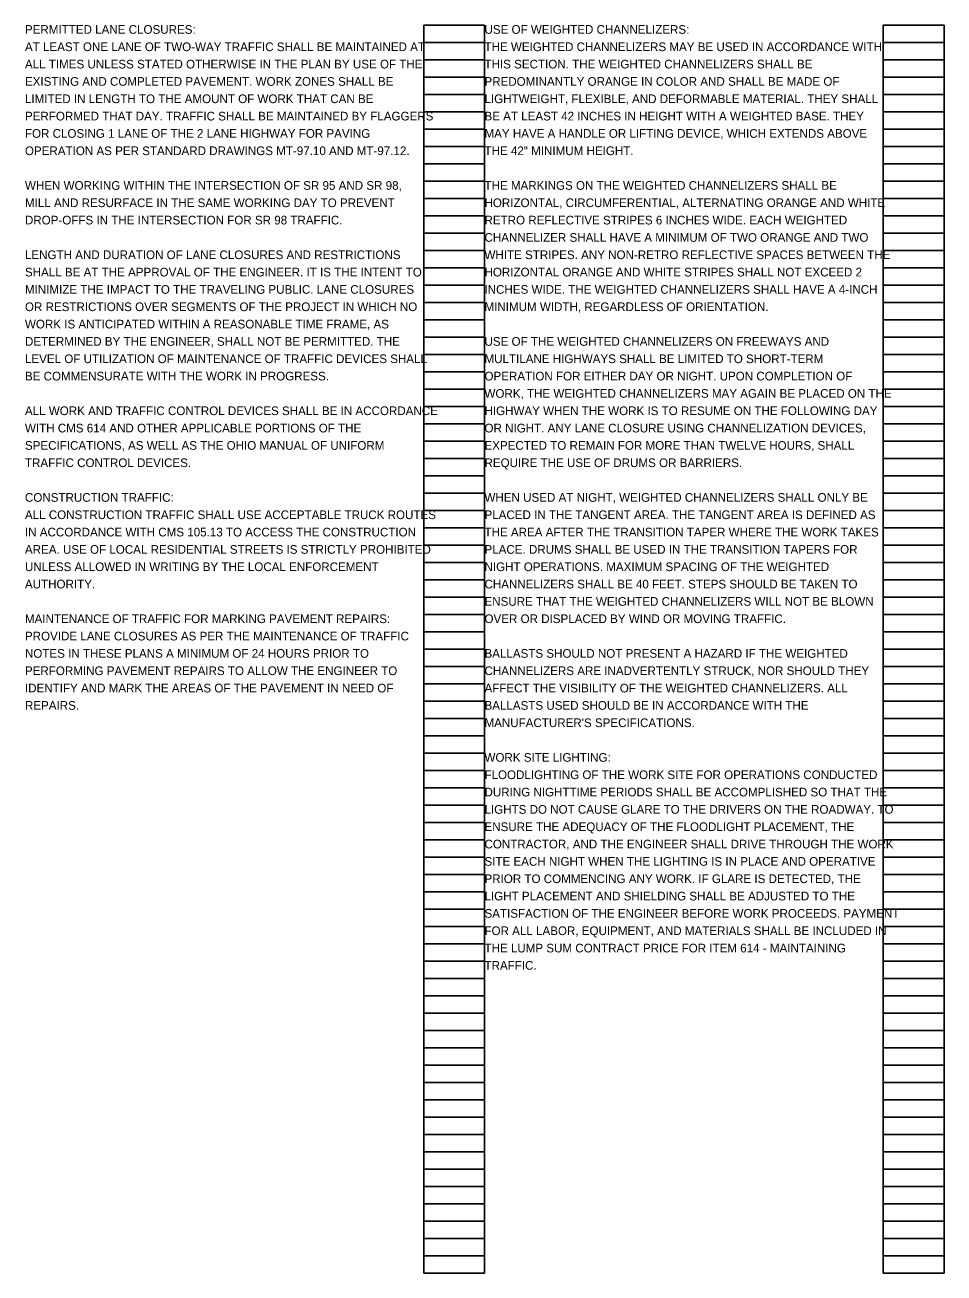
# Model space of a CAD drawing. Extents: x -23 to 32, y -58.1 to 21.1.
# Drawn here: x 2.4 to 17.24, y -28.09 to -7.93 of the extents above; entities that cross this region are included whole.
import ezdxf

# ---------------------------------------------------------------- set-up
doc = ezdxf.new("R2010")
doc.units = 0
doc.layers.add('SH_Data', color=7, linetype='Continuous')
doc.layers.add('SH_Text', color=7, linetype='Continuous')

msp = doc.modelspace()

# ---------------------------------------------------------------- linework, layer by layer
at = {"layer": 'SH_Data'}
for p, q in [((8.84, -28.093), (8.84, -7.933)), ((8.84, -7.933), (9.82, -7.933)), ((9.82, -28.093), (9.82, -7.933)), ((16.26, -28.093), (16.26, -7.933)), ((16.26, -7.933), (17.24, -7.933)), ((17.24, -28.093), (17.24, -7.933)), ((8.84, -8.213), (9.82, -8.213)), ((16.26, -8.213), (17.24, -8.213)), ((8.84, -8.493), (9.82, -8.493)), ((16.26, -8.493), (17.24, -8.493)), ((8.84, -8.773), (9.82, -8.773)), ((16.26, -8.773), (17.24, -8.773)), ((8.84, -9.053), (9.82, -9.053)), ((16.26, -9.053), (17.24, -9.053)), ((8.84, -9.333), (9.82, -9.333)), ((16.26, -9.333), (17.24, -9.333)), ((8.84, -9.613), (9.82, -9.613)), ((16.26, -9.613), (17.24, -9.613)), ((8.84, -9.893), (9.82, -9.893)), ((16.26, -9.893), (17.24, -9.893)), ((8.84, -10.173), (9.82, -10.173)), ((16.26, -10.173), (17.24, -10.173)), ((8.84, -10.453), (9.82, -10.453)), ((16.26, -10.453), (17.24, -10.453)), ((8.84, -10.733), (9.82, -10.733)), ((16.26, -10.733), (17.24, -10.733)), ((8.84, -11.013), (9.82, -11.013)), ((16.26, -11.013), (17.24, -11.013)), ((8.84, -11.293), (9.82, -11.293)), ((16.26, -11.293), (17.24, -11.293)), ((8.84, -11.573), (9.82, -11.573)), ((16.26, -11.573), (17.24, -11.573)), ((8.84, -11.853), (9.82, -11.853)), ((16.26, -11.853), (17.24, -11.853)), ((8.84, -12.133), (9.82, -12.133)), ((16.26, -12.133), (17.24, -12.133)), ((8.84, -12.413), (9.82, -12.413)), ((16.26, -12.413), (17.24, -12.413)), ((8.84, -12.693), (9.82, -12.693)), ((16.26, -12.693), (17.24, -12.693)), ((8.84, -12.973), (9.82, -12.973)), ((16.26, -12.973), (17.24, -12.973)), ((8.84, -13.253), (9.82, -13.253)), ((16.26, -13.253), (17.24, -13.253)), ((8.84, -13.533), (9.82, -13.533)), ((16.26, -13.533), (17.24, -13.533)), ((8.84, -13.813), (9.82, -13.813)), ((16.26, -13.813), (17.24, -13.813)), ((8.84, -14.093), (9.82, -14.093)), ((16.26, -14.093), (17.24, -14.093)), ((8.84, -14.373), (9.82, -14.373)), ((16.26, -14.373), (17.24, -14.373)), ((8.84, -14.653), (9.82, -14.653)), ((16.26, -14.653), (17.24, -14.653)), ((8.84, -14.933), (9.82, -14.933)), ((16.26, -14.933), (17.24, -14.933)), ((8.84, -15.213), (9.82, -15.213)), ((16.26, -15.213), (17.24, -15.213)), ((8.84, -15.493), (9.82, -15.493)), ((16.26, -15.493), (17.24, -15.493)), ((8.84, -15.773), (9.82, -15.773)), ((16.26, -15.773), (17.24, -15.773)), ((8.84, -16.053), (9.82, -16.053)), ((16.26, -16.053), (17.24, -16.053)), ((8.84, -16.333), (9.82, -16.333)), ((16.26, -16.333), (17.24, -16.333)), ((8.84, -16.613), (9.82, -16.613)), ((16.26, -16.613), (17.24, -16.613)), ((8.84, -16.893), (9.82, -16.893)), ((16.26, -16.893), (17.24, -16.893)), ((8.84, -17.173), (9.82, -17.173)), ((16.26, -17.173), (17.24, -17.173)), ((8.84, -17.453), (9.82, -17.453)), ((16.26, -17.453), (17.24, -17.453)), ((8.84, -17.733), (9.82, -17.733)), ((16.26, -17.733), (17.24, -17.733)), ((8.84, -18.013), (9.82, -18.013)), ((16.26, -18.013), (17.24, -18.013)), ((8.84, -18.293), (9.82, -18.293)), ((16.26, -18.293), (17.24, -18.293)), ((8.84, -18.573), (9.82, -18.573)), ((16.26, -18.573), (17.24, -18.573)), ((8.84, -18.853), (9.82, -18.853)), ((16.26, -18.853), (17.24, -18.853)), ((8.84, -19.133), (9.82, -19.133)), ((16.26, -19.133), (17.24, -19.133)), ((8.84, -19.413), (9.82, -19.413)), ((16.26, -19.413), (17.24, -19.413)), ((8.84, -19.693), (9.82, -19.693)), ((16.26, -19.693), (17.24, -19.693)), ((8.84, -19.973), (9.82, -19.973)), ((16.26, -19.973), (17.24, -19.973)), ((8.84, -20.253), (9.82, -20.253)), ((16.26, -20.253), (17.24, -20.253)), ((8.84, -20.533), (9.82, -20.533)), ((16.26, -20.533), (17.24, -20.533)), ((8.84, -20.813), (9.82, -20.813)), ((16.26, -20.813), (17.24, -20.813)), ((8.84, -21.093), (9.82, -21.093)), ((16.26, -21.093), (17.24, -21.093)), ((8.84, -21.373), (9.82, -21.373)), ((16.26, -21.373), (17.24, -21.373)), ((8.84, -21.653), (9.82, -21.653)), ((16.26, -21.653), (17.24, -21.653)), ((8.84, -21.933), (9.82, -21.933)), ((16.26, -21.933), (17.24, -21.933)), ((8.84, -22.213), (9.82, -22.213)), ((16.26, -22.213), (17.24, -22.213)), ((8.84, -22.493), (9.82, -22.493)), ((16.26, -22.493), (17.24, -22.493)), ((8.84, -22.773), (9.82, -22.773)), ((16.26, -22.773), (17.24, -22.773)), ((8.84, -23.053), (9.82, -23.053)), ((16.26, -23.053), (17.24, -23.053)), ((8.84, -23.333), (9.82, -23.333)), ((16.26, -23.333), (17.24, -23.333)), ((8.84, -23.613), (9.82, -23.613)), ((16.26, -23.613), (17.24, -23.613)), ((8.84, -23.893), (9.82, -23.893)), ((16.26, -23.893), (17.24, -23.893)), ((8.84, -24.173), (9.82, -24.173)), ((16.26, -24.173), (17.24, -24.173)), ((8.84, -24.453), (9.82, -24.453)), ((16.26, -24.453), (17.24, -24.453)), ((8.84, -24.733), (9.82, -24.733)), ((16.26, -24.733), (17.24, -24.733)), ((8.84, -25.013), (9.82, -25.013)), ((16.26, -25.013), (17.24, -25.013)), ((8.84, -25.293), (9.82, -25.293)), ((16.26, -25.293), (17.24, -25.293)), ((8.84, -25.573), (9.82, -25.573)), ((16.26, -25.573), (17.24, -25.573)), ((8.84, -25.853), (9.82, -25.853)), ((16.26, -25.853), (17.24, -25.853)), ((8.84, -26.133), (9.82, -26.133)), ((16.26, -26.133), (17.24, -26.133)), ((8.84, -26.413), (9.82, -26.413)), ((16.26, -26.413), (17.24, -26.413)), ((8.84, -26.693), (9.82, -26.693)), ((16.26, -26.693), (17.24, -26.693)), ((8.84, -26.973), (9.82, -26.973)), ((16.26, -26.973), (17.24, -26.973)), ((8.84, -27.253), (9.82, -27.253)), ((16.26, -27.253), (17.24, -27.253)), ((8.84, -27.533), (9.82, -27.533)), ((16.26, -27.533), (17.24, -27.533)), ((8.84, -27.813), (9.82, -27.813)), ((16.26, -27.813), (17.24, -27.813)), ((8.84, -28.093), (9.82, -28.093)), ((16.26, -28.093), (17.24, -28.093))]:
    msp.add_line(p, q, dxfattribs=at)

# ---------------------------------------------------------------- texts
at = {"layer": 'SH_Text'}
for s, p in [('PERMITTED LANE CLOSURES:', (2.4, -8.073)), ('USE OF WEIGHTED CHANNELIZERS:', (9.82, -8.073)), ('AT LEAST ONE LANE OF TWO-WAY TRAFFIC SHALL BE MAINTAINED AT ', (2.4, -8.353)), ('THE WEIGHTED CHANNELIZERS MAY BE USED IN ACCORDANCE WITH ', (9.82, -8.353)), ('ALL TIMES UNLESS STATED OTHERWISE IN THE PLAN BY USE OF THE ', (2.4, -8.633)), ('THIS SECTION. THE WEIGHTED CHANNELIZERS SHALL BE ', (9.82, -8.633)), ('EXISTING AND COMPLETED PAVEMENT. WORK ZONES SHALL BE ', (2.4, -8.913)), ('PREDOMINANTLY ORANGE IN COLOR AND SHALL BE MADE OF ', (9.82, -8.913)), ('LIMITED IN LENGTH TO THE AMOUNT OF WORK THAT CAN BE ', (2.4, -9.193)), ('LIGHTWEIGHT, FLEXIBLE, AND DEFORMABLE MATERIAL. THEY SHALL ', (9.82, -9.193)), ('PERFORMED THAT DAY. TRAFFIC SHALL BE MAINTAINED BY FLAGGERS ', (2.4, -9.473)), ('BE AT LEAST 42 INCHES IN HEIGHT WITH A WEIGHTED BASE. THEY ', (9.82, -9.473)), ('FOR CLOSING 1 LANE OF THE 2 LANE HIGHWAY FOR PAVING ', (2.4, -9.753)), ('MAY HAVE A HANDLE OR LIFTING DEVICE, WHICH EXTENDS ABOVE ', (9.82, -9.753)), ('OPERATION AS PER STANDARD DRAWINGS MT-97.10 AND MT-97.12. ', (2.4, -10.033)), ('THE 42" MINIMUM HEIGHT.', (9.82, -10.033)), ('WHEN WORKING WITHIN THE INTERSECTION OF SR 95 AND SR 98, ', (2.4, -10.593)), ('THE MARKINGS ON THE WEIGHTED CHANNELIZERS SHALL BE ', (9.82, -10.593)), ('MILL AND RESURFACE IN THE SAME WORKING DAY TO PREVENT ', (2.4, -10.873)), ('HORIZONTAL, CIRCUMFERENTIAL, ALTERNATING ORANGE AND WHITE ', (9.82, -10.873)), ('DROP-OFFS IN THE INTERSECTION FOR SR 98 TRAFFIC.', (2.4, -11.153)), ('RETRO REFLECTIVE STRIPES 6 INCHES WIDE. EACH WEIGHTED ', (9.82, -11.153)), ('CHANNELIZER SHALL HAVE A MINIMUM OF TWO ORANGE AND TWO ', (9.82, -11.433)), ('LENGTH AND DURATION OF LANE CLOSURES AND RESTRICTIONS ', (2.4, -11.713)), ('WHITE STRIPES. ANY NON-RETRO REFLECTIVE SPACES BETWEEN THE ', (9.82, -11.713)), ('SHALL BE AT THE APPROVAL OF THE ENGINEER. IT IS THE INTENT TO ', (2.4, -11.993)), ('HORIZONTAL ORANGE AND WHITE STRIPES SHALL NOT EXCEED 2 ', (9.82, -11.993)), ('MINIMIZE THE IMPACT TO THE TRAVELING PUBLIC. LANE CLOSURES ', (2.4, -12.273)), ('INCHES WIDE. THE WEIGHTED CHANNELIZERS SHALL HAVE A 4-INCH ', (9.82, -12.273)), ('OR RESTRICTIONS OVER SEGMENTS OF THE PROJECT IN WHICH NO ', (2.4, -12.553)), ('MINIMUM WIDTH, REGARDLESS OF ORIENTATION.', (9.82, -12.553)), ('WORK IS ANTICIPATED WITHIN A REASONABLE TIME FRAME, AS ', (2.4, -12.833)), ('DETERMINED BY THE ENGINEER, SHALL NOT BE PERMITTED. THE ', (2.4, -13.113)), ('USE OF THE WEIGHTED CHANNELIZERS ON FREEWAYS AND ', (9.82, -13.113)), ('LEVEL OF UTILIZATION OF MAINTENANCE OF TRAFFIC DEVICES SHALL ', (2.4, -13.393)), ('MULTILANE HIGHWAYS SHALL BE LIMITED TO SHORT-TERM ', (9.82, -13.393)), ('BE COMMENSURATE WITH THE WORK IN PROGRESS.', (2.4, -13.673)), ('OPERATION FOR EITHER DAY OR NIGHT. UPON COMPLETION OF ', (9.82, -13.673)), ('WORK, THE WEIGHTED CHANNELIZERS MAY AGAIN BE PLACED ON THE ', (9.82, -13.953)), ('ALL WORK AND TRAFFIC CONTROL DEVICES SHALL BE IN ACCORDANCE ', (2.4, -14.233)), ('HIGHWAY WHEN THE WORK IS TO RESUME ON THE FOLLOWING DAY ', (9.82, -14.233)), ('WITH CMS 614 AND OTHER APPLICABLE PORTIONS OF THE ', (2.4, -14.513)), ('OR NIGHT. ANY LANE CLOSURE USING CHANNELIZATION DEVICES, ', (9.82, -14.513)), ('SPECIFICATIONS, AS WELL AS THE OHIO MANUAL OF UNIFORM ', (2.4, -14.793)), ('EXPECTED TO REMAIN FOR MORE THAN TWELVE HOURS, SHALL ', (9.82, -14.793)), ('TRAFFIC CONTROL DEVICES.', (2.4, -15.073)), ('REQUIRE THE USE OF DRUMS OR BARRIERS.', (9.82, -15.073)), ('CONSTRUCTION TRAFFIC:', (2.4, -15.633)), ('WHEN USED AT NIGHT, WEIGHTED CHANNELIZERS SHALL ONLY BE ', (9.82, -15.633)), ('ALL CONSTRUCTION TRAFFIC SHALL USE ACCEPTABLE TRUCK ROUTES ', (2.4, -15.913)), ('PLACED IN THE TANGENT AREA. THE TANGENT AREA IS DEFINED AS ', (9.82, -15.913)), ('IN ACCORDANCE WITH CMS 105.13 TO ACCESS THE CONSTRUCTION ', (2.4, -16.193)), ('THE AREA AFTER THE TRANSITION TAPER WHERE THE WORK TAKES ', (9.82, -16.193)), ('AREA. USE OF LOCAL RESIDENTIAL STREETS IS STRICTLY PROHIBITED ', (2.4, -16.473)), ('PLACE. DRUMS SHALL BE USED IN THE TRANSITION TAPERS FOR ', (9.82, -16.473)), ('UNLESS ALLOWED IN WRITING BY THE LOCAL ENFORCEMENT ', (2.4, -16.753)), ('NIGHT OPERATIONS. MAXIMUM SPACING OF THE WEIGHTED ', (9.82, -16.753)), ('AUTHORITY.', (2.4, -17.033)), ('CHANNELIZERS SHALL BE 40 FEET. STEPS SHOULD BE TAKEN TO ', (9.82, -17.033)), ('ENSURE THAT THE WEIGHTED CHANNELIZERS WILL NOT BE BLOWN ', (9.82, -17.313)), ('MAINTENANCE OF TRAFFIC FOR MARKING PAVEMENT REPAIRS:', (2.4, -17.593)), ('OVER OR DISPLACED BY WIND OR MOVING TRAFFIC.', (9.82, -17.593)), ('PROVIDE LANE CLOSURES AS PER THE MAINTENANCE OF TRAFFIC ', (2.4, -17.873)), ('NOTES IN THESE PLANS A MINIMUM OF 24 HOURS PRIOR TO ', (2.4, -18.153)), ('BALLASTS SHOULD NOT PRESENT A HAZARD IF THE WEIGHTED ', (9.82, -18.153)), ('PERFORMING PAVEMENT REPAIRS TO ALLOW THE ENGINEER TO ', (2.4, -18.433)), ('CHANNELIZERS ARE INADVERTENTLY STRUCK, NOR SHOULD THEY ', (9.82, -18.433)), ('IDENTIFY AND MARK THE AREAS OF THE PAVEMENT IN NEED OF ', (2.4, -18.713)), ('AFFECT THE VISIBILITY OF THE WEIGHTED CHANNELIZERS. ALL ', (9.82, -18.713)), ('REPAIRS.', (2.4, -18.993)), ('BALLASTS USED SHOULD BE IN ACCORDANCE WITH THE ', (9.82, -18.993)), ("MANUFACTURER'S SPECIFICATIONS.", (9.82, -19.273)), ('WORK SITE LIGHTING:', (9.82, -19.833)), ('FLOODLIGHTING OF THE WORK SITE FOR OPERATIONS CONDUCTED ', (9.82, -20.113)), ('DURING NIGHTTIME PERIODS SHALL BE ACCOMPLISHED SO THAT THE ', (9.82, -20.393)), ('LIGHTS DO NOT CAUSE GLARE TO THE DRIVERS ON THE ROADWAY. TO ', (9.82, -20.673)), ('ENSURE THE ADEQUACY OF THE FLOODLIGHT PLACEMENT, THE ', (9.82, -20.953)), ('CONTRACTOR, AND THE ENGINEER SHALL DRIVE THROUGH THE WORK ', (9.82, -21.233)), ('SITE EACH NIGHT WHEN THE LIGHTING IS IN PLACE AND OPERATIVE ', (9.82, -21.513)), ('PRIOR TO COMMENCING ANY WORK. IF GLARE IS DETECTED, THE ', (9.82, -21.793)), ('LIGHT PLACEMENT AND SHIELDING SHALL BE ADJUSTED TO THE ', (9.82, -22.073)), ('SATISFACTION OF THE ENGINEER BEFORE WORK PROCEEDS. PAYMENT ', (9.82, -22.353)), ('FOR ALL LABOR, EQUIPMENT, AND MATERIALS SHALL BE INCLUDED IN ', (9.82, -22.633)), ('THE LUMP SUM CONTRACT PRICE FOR ITEM 614 - MAINTAINING ', (9.82, -22.913)), ('TRAFFIC.', (9.82, -23.193))]:
    msp.add_text(s, height=0.14, dxfattribs=at).set_placement(p)

doc.saveas('drawing.dxf')
